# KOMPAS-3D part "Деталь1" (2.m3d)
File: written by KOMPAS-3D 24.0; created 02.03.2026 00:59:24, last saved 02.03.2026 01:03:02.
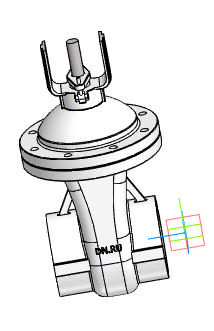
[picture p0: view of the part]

Document properties: Автор: R2D2; Полное имя файла: E:\Работа\Зайцев\GVWR3131M-2W-F-S Задвижка клиновая с выдвижным штоком DN.ru Ду50-200 Ру63\DN100\исходные материалы\2.m3d

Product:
- Body: Твердое тело1  | qty 1
    Масса: 0.571095
- Part/product: Деталь1
    Масса: 0.571095
    additional columns: Типовые

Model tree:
1. Твердое тело1  (labels: Твердое тело1)
2. Эскиз:1
3. Элемент выдавливания:2
     Расстояние 1 = 500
